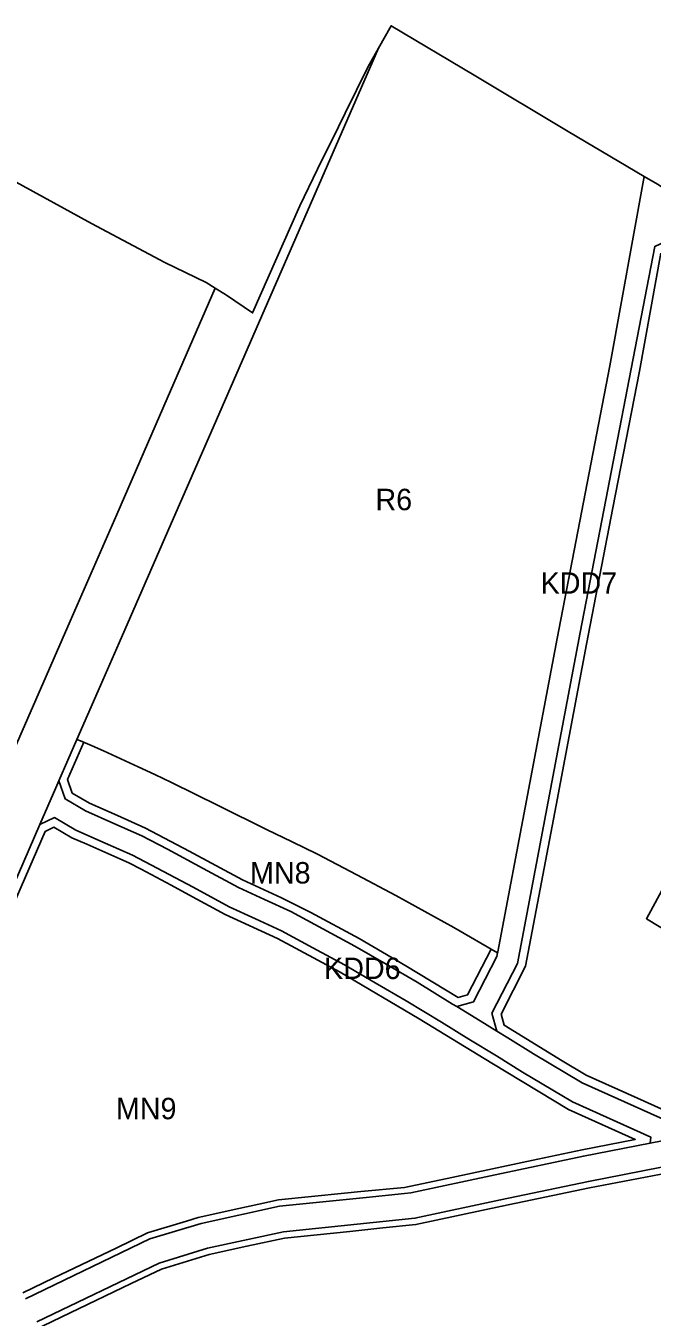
# Model space of a CAD drawing. Extents: x 7439486 to 7443435, y 5551288 to 5554556.
# Drawn here: x 7441363 to 7441655, y 5553244 to 5553846 of the extents above; entities that cross this region are included whole.
import ezdxf

# ---------------------------------------------------------------- set-up
doc = ezdxf.new("R2010")
doc.units = 0
for name, color, linetype in [('linie_rozgraniczajace', 7, 'Continuous'), ('linie_zabudowy_nieprzekraczalne', 7, 'Continuous'), ('oznaczenia_przeznaczen', 7, 'Continuous')]:
    doc.layers.add(name, color=color, linetype=linetype)

msp = doc.modelspace()

# ---------------------------------------------------------------- linework, layer by layer
at = {"layer": 'linie_rozgraniczajace'}
for points in [[(7441386.9, 5553513.44), (7441396.83, 5553536.2), (7441406.6, 5553558.6), (7441429.27, 5553610.58), (7441451.94, 5553662.56), (7441527.59, 5553836.01), (7441533.48, 5553846.42), (7441572.18, 5553823.43), (7441615.98, 5553797.19), (7441651.46, 5553776.19), (7441635.49, 5553687.72), (7441610.84, 5553560.54), (7441583.19, 5553414.34), (7441583.1, 5553413.85), (7441562.7, 5553425.62), (7441549.2, 5553433.1), (7441535.7, 5553440.59), (7441517.42, 5553450.23), (7441499.13, 5553459.88), (7441487.21, 5553465.65), (7441475.29, 5553471.42), (7441453.15, 5553482.41), (7441431.02, 5553493.4), (7441423.21, 5553497.03), (7441415.4, 5553500.66), (7441407.36, 5553504.4), (7441399.32, 5553508.14), (7441393.92, 5553510.44), (7441388.52, 5553512.75)], [(7441564.02, 5553388.84), (7441571.87, 5553390.96), (7441582.79, 5553412.21), (7441583.1, 5553413.85), (7441583.19, 5553414.34), (7441610.84, 5553560.54), (7441635.49, 5553687.72), (7441651.46, 5553776.19), (7441657.69, 5553772.51), (7441659.87, 5553771.21), (7441661.04, 5553770.52), (7441661.58, 5553770.2), (7441661.94, 5553769.99), (7441670.74, 5553764.84), (7441666.72, 5553744.02), (7441662.75, 5553746.34), (7441656.43, 5553743.48), (7441621.66, 5553563.33), (7441592.35, 5553408.93), (7441580.43, 5553385.74), (7441582.74, 5553377.39), (7441574.96, 5553382.15), (7441564.12, 5553388.78)], [(7441378.51, 5553494.19), (7441386.9, 5553513.44), (7441388.52, 5553512.75), (7441393.92, 5553510.44), (7441399.32, 5553508.14), (7441407.36, 5553504.4), (7441415.4, 5553500.66), (7441423.21, 5553497.03), (7441431.02, 5553493.4), (7441453.15, 5553482.41), (7441475.29, 5553471.42), (7441487.21, 5553465.65), (7441499.13, 5553459.88), (7441517.42, 5553450.23), (7441535.7, 5553440.59), (7441549.2, 5553433.1), (7441562.7, 5553425.62), (7441583.1, 5553413.85), (7441582.79, 5553412.21), (7441571.87, 5553390.96), (7441564.02, 5553388.84), (7441562.13, 5553390), (7441553.87, 5553395.05), (7441553.75, 5553395.12), (7441545.55, 5553400.13), (7441531.05, 5553408.58), (7441516.52, 5553417.05), (7441501.65, 5553425.07), (7441486.71, 5553433.12), (7441474.33, 5553438.81), (7441462.3, 5553444.34), (7441445.79, 5553453.25), (7441429.06, 5553462.28), (7441417.16, 5553468.48), (7441404.12, 5553474.24), (7441390.91, 5553480.07), (7441381.32, 5553485.7)]]:
    msp.add_lwpolyline(points, close=True, dxfattribs=at)
for points in [[(7441356.47, 5553506.19), (7441383.69, 5553568.6), (7441405.45, 5553618.48), (7441429.03, 5553672.55), (7441451.44, 5553723.94), (7441456.66, 5553720.68), (7441468.8, 5553712.48), (7441490.78, 5553762.48), (7441499.14, 5553779.48), (7441508.89, 5553799.32), (7441511.98, 5553805.6), (7441522.58, 5553827.16), (7441527.59, 5553836.01), (7441451.94, 5553662.56), (7441429.27, 5553610.58), (7441406.6, 5553558.6), (7441396.83, 5553536.2), (7441386.9, 5553513.44), (7441378.51, 5553494.19), (7441377.05, 5553490.84), (7441369.63, 5553473.83), (7441347.49, 5553423.07)], [(7441344, 5553781.42), (7441393.68, 5553754.13), (7441427.81, 5553735.95), (7441447.15, 5553726.63), (7441451.44, 5553723.94), (7441429.03, 5553672.55), (7441405.45, 5553618.48), (7441383.69, 5553568.6), (7441356.47, 5553506.19)], [(7441671.1, 5553331.46), (7441622.6, 5553353.22), (7441599.9, 5553366.73), (7441587.82, 5553374.29), (7441582.74, 5553377.39), (7441580.43, 5553385.74), (7441592.35, 5553408.93), (7441621.66, 5553563.33), (7441656.43, 5553743.48)], [(7441681.45, 5553330.41), (7441654.23, 5553325.09), (7441654.57, 5553327.92), (7441617.98, 5553344.33), (7441594.69, 5553358.2), (7441582.56, 5553365.79), (7441569.75, 5553373.62), (7441556.91, 5553381.47), (7441548.65, 5553386.51), (7441540.43, 5553391.54), (7441526.02, 5553399.94), (7441511.63, 5553408.33), (7441496.91, 5553416.26), (7441482.24, 5553424.17), (7441470.15, 5553429.73), (7441457.84, 5553435.39), (7441441.04, 5553444.45), (7441424.38, 5553453.45), (7441412.83, 5553459.46), (7441400.08, 5553465.09), (7441386.35, 5553471.16), (7441376.38, 5553477.01), (7441369.63, 5553473.83), (7441377.05, 5553490.84), (7441378.51, 5553494.19), (7441381.32, 5553485.7), (7441390.91, 5553480.07), (7441404.12, 5553474.24), (7441417.16, 5553468.48), (7441429.06, 5553462.28), (7441445.79, 5553453.25), (7441462.3, 5553444.34), (7441474.33, 5553438.81), (7441486.71, 5553433.12), (7441501.65, 5553425.07), (7441516.52, 5553417.05), (7441531.05, 5553408.58), (7441545.55, 5553400.13), (7441553.75, 5553395.12), (7441553.87, 5553395.05), (7441562.13, 5553390), (7441564.02, 5553388.84), (7441564.12, 5553388.78), (7441574.96, 5553382.15), (7441582.74, 5553377.39), (7441587.82, 5553374.29), (7441599.9, 5553366.73), (7441622.6, 5553353.22), (7441671.1, 5553331.46)], [(7441347.49, 5553423.07), (7441369.63, 5553473.83), (7441376.38, 5553477.01), (7441386.35, 5553471.16), (7441400.08, 5553465.09), (7441412.83, 5553459.46), (7441424.38, 5553453.45), (7441441.04, 5553444.45), (7441457.84, 5553435.39), (7441470.15, 5553429.73), (7441482.24, 5553424.17), (7441496.91, 5553416.26), (7441511.63, 5553408.33), (7441526.02, 5553399.94), (7441540.43, 5553391.54), (7441548.65, 5553386.51), (7441556.91, 5553381.47), (7441569.75, 5553373.62), (7441582.56, 5553365.79), (7441594.69, 5553358.2), (7441617.98, 5553344.33), (7441654.57, 5553327.92), (7441654.23, 5553325.09), (7441623.13, 5553319.01), (7441582.01, 5553310.29), (7441542.65, 5553301.93), (7441539.6, 5553301.62), (7441521.82, 5553299.79), (7441481.35, 5553295.62), (7441444.81, 5553287.65), (7441420.83, 5553280.36), (7441362.94, 5553252.51)], [(7441362.94, 5553252.51), (7441420.83, 5553280.36), (7441444.81, 5553287.65), (7441481.35, 5553295.62), (7441521.82, 5553299.79), (7441539.6, 5553301.62), (7441542.65, 5553301.93), (7441582.01, 5553310.29), (7441623.13, 5553319.01), (7441654.23, 5553325.09), (7441681.45, 5553330.41)], [(7441368.14, 5553241.69), (7441425.2, 5553269.15), (7441447.84, 5553276.03), (7441483.25, 5553283.76), (7441544.51, 5553290.06), (7441584.5, 5553298.55), (7441625.43, 5553307.24), (7441692.79, 5553320.41)], [(7441692.79, 5553320.41), (7441625.43, 5553307.24), (7441584.5, 5553298.55), (7441544.51, 5553290.06), (7441483.25, 5553283.76), (7441447.84, 5553276.03), (7441425.2, 5553269.15), (7441368.14, 5553241.69)]]:
    msp.add_lwpolyline(points, dxfattribs=at)
at = {"layer": 'linie_zabudowy_nieprzekraczalne'}
for points in [[(7441659.21, 5553740.35), (7441654.24, 5553712.79), (7441649.26, 5553685.24), (7441636.91, 5553621.47), (7441624.58, 5553557.87), (7441610.38, 5553482.78), (7441596.17, 5553407.61), (7441584.7, 5553385.3), (7441586.16, 5553380.05), (7441613.21, 5553363.46), (7441624.44, 5553356.78), (7441648.3, 5553346.08), (7441672.15, 5553335.37)], [(7441580.04, 5553415.61), (7441569.11, 5553394.34), (7441564.72, 5553393.1), (7441540.34, 5553407.8), (7441518.48, 5553420.54), (7441496.02, 5553432.64), (7441482.25, 5553439.57), (7441464.09, 5553447.92), (7441439.31, 5553461.29), (7441418.9, 5553472.09), (7441405.73, 5553477.9), (7441392.74, 5553483.64), (7441384.65, 5553488.39), (7441382.55, 5553494.71), (7441390.15, 5553512.12)], [(7441347.47, 5553414.25), (7441372.01, 5553470.53), (7441376.17, 5553472.49), (7441384.52, 5553467.59), (7441391.49, 5553464.51), (7441398.46, 5553461.44), (7441411.1, 5553455.86), (7441416.8, 5553452.88), (7441430.82, 5553445.42), (7441439.14, 5553440.93), (7441456.05, 5553431.81), (7441480.45, 5553420.59), (7441509.67, 5553404.84), (7441546.57, 5553383.1), (7441580.46, 5553362.38), (7441616.13, 5553340.78), (7441647.3, 5553326.8), (7441622.55, 5553321.96), (7441601.85, 5553317.57), (7441561.78, 5553309.06), (7441539.67, 5553304.36), (7441519.28, 5553302.54)], [(7441668.75, 5553419.87), (7441652.5, 5553429.75), (7441659.7, 5553442.99)], [(7441332.65, 5553221.29), (7441383.71, 5553245.85), (7441412.13, 5553259.53), (7441426.29, 5553266.34), (7441448.59, 5553273.12), (7441466.19, 5553276.96), (7441483.73, 5553280.79), (7441498.96, 5553282.36), (7441514.19, 5553283.92), (7441529.58, 5553285.51), (7441544.98, 5553287.09), (7441585.12, 5553295.61), (7441626.02, 5553304.3), (7441674.9, 5553313.55)], [(7441519.28, 5553302.54), (7441511.69, 5553301.76), (7441496.29, 5553300.18), (7441480.88, 5553298.59), (7441471.66, 5553296.58), (7441462.44, 5553294.57), (7441443.41, 5553290.41), (7441438, 5553288.71), (7441419.74, 5553283.16), (7441405.16, 5553276.15), (7441376.11, 5553262.17), (7441361.64, 5553255.21)]]:
    msp.add_lwpolyline(points, dxfattribs=at)

# ---------------------------------------------------------------- texts
at = {"layer": 'oznaczenia_przeznaczen'}
for s, p in [('R6', (7441526.14, 5553620.4)), ('KDD7', (7441603.19, 5553581.45)), ('MN8', (7441467.62, 5553446.22)), ('KDD6', (7441502.19, 5553401.65)), ('MN9', (7441405.08, 5553336.23))]:
    msp.add_text(s, height=10, dxfattribs=at).set_placement(p)

doc.saveas('drawing.dxf')
